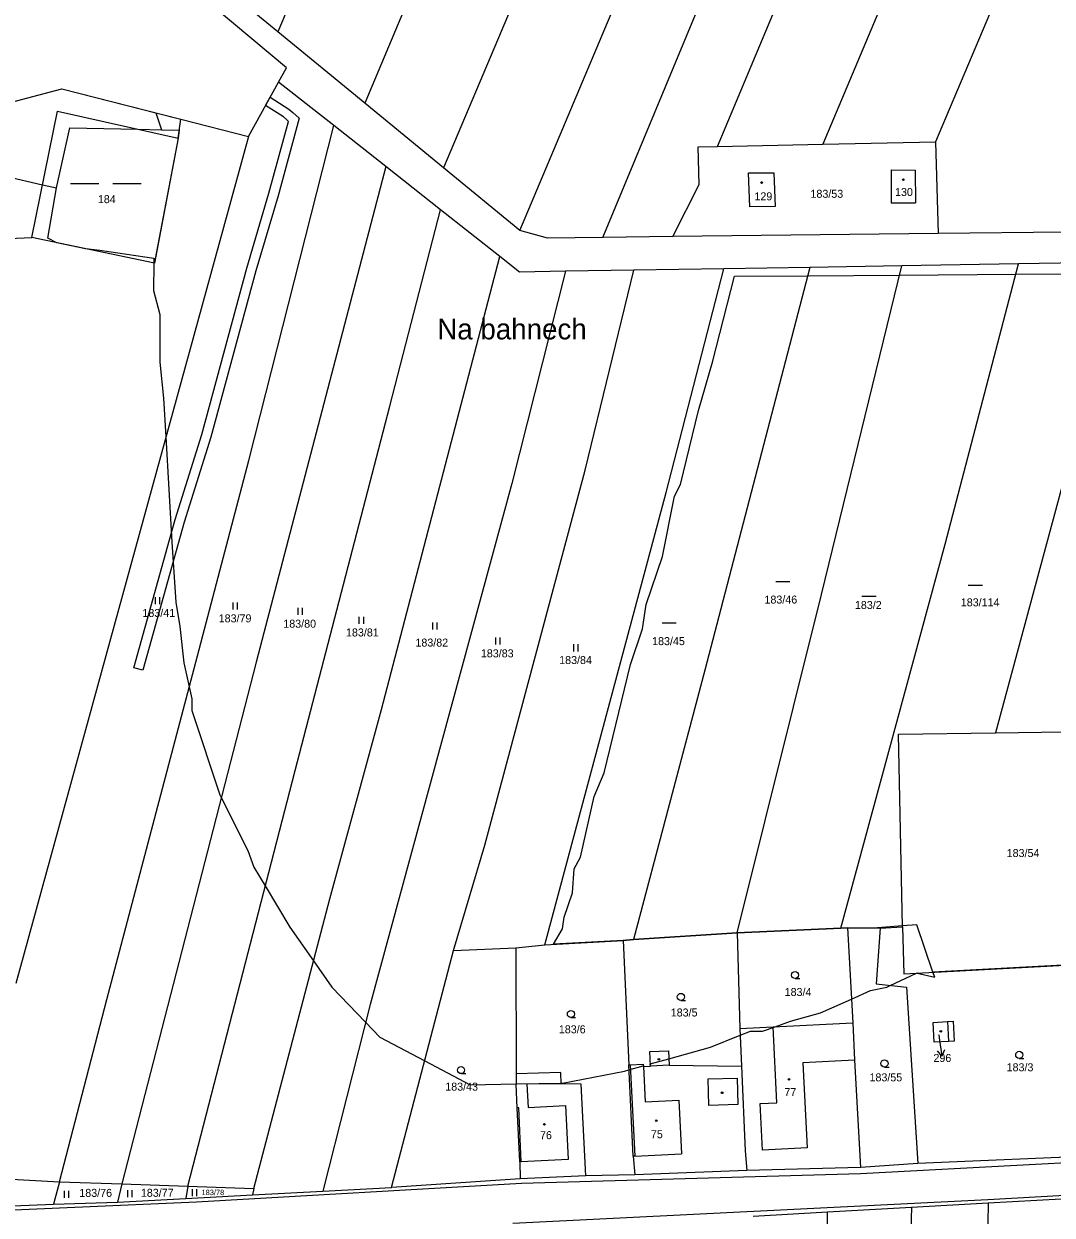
# Model space of a CAD drawing. Extents: x -747333 to -745433, y -1133152 to -1130600.
# Drawn here: x -747031.5 to -746813.1, y -1132285.5 to -1132032.4 of the extents above; entities that cross this region are included whole.
import ezdxf

# ---------------------------------------------------------------- set-up
doc = ezdxf.new("R2010")
doc.units = 0
for name, color, linetype in [('Vrstva 1', 7, 'Continuous'), ('Vrstva 13', 7, 'Continuous'), ('Vrstva 15', 7, 'Continuous'), ('Vrstva 16', 7, 'Continuous'), ('Vrstva 18', 7, 'Continuous'), ('Vrstva 19', 7, 'Continuous'), ('Vrstva 25', 7, 'Continuous'), ('Vrstva 3', 7, 'Continuous'), ('Vrstva 30', 7, 'Continuous'), ('Vrstva 37', 7, 'Continuous'), ('Vrstva 4', 7, 'Continuous'), ('Vrstva 52', 7, 'Continuous'), ('Vrstva 6', 7, 'Continuous')]:
    doc.layers.add(name, color=color, linetype=linetype)

msp = doc.modelspace()

# ---------------------------------------------------------------- linework, layer by layer
at = {"layer": 'Vrstva 1'}
for points in [[(-746977.55, -1132034.06), (-746997.36, -1132017.78)], [(-746959.07, -1132049.24), (-746977.55, -1132034.06)], [(-746965.7, -1132053.97), (-746977.4, -1132044.75)], [(-746942.38, -1132062.95), (-746959.07, -1132049.24)], [(-747029.81, -1132077.77), (-747024.36, -1132050.95)], [(-747024.36, -1132050.95), (-746998.74, -1132056.7)], [(-746998.74, -1132056.7), (-746998.16, -1132052.61)], [(-746954.65, -1132062.68), (-746965.7, -1132053.97)], [(-746983.8, -1132056.28), (-747014.12, -1132166.6)], [(-746998.74, -1132056.7), (-747003.78, -1132083.21)], [(-746884.2, -1132058.41), (-746861.84, -1132057.93)], [(-746861.84, -1132057.93), (-746837.88, -1132057.42)], [(-746837.88, -1132057.42), (-746837.35, -1132076.92)], [(-746888.32, -1132058.5), (-746884.2, -1132058.41)], [(-746888.09, -1132066.49), (-746888.32, -1132058.5)], [(-746942.98, -1132071.88), (-746954.65, -1132062.68)], [(-746926.18, -1132076.31), (-746942.38, -1132062.95)], [(-746877.57, -1132064.03), (-746872.2, -1132064.03)], [(-746877.34, -1132071.25), (-746877.57, -1132064.03)], [(-746872.2, -1132064.03), (-746871.97, -1132071.17)], [(-746847.33, -1132063.4), (-746842.21, -1132063.47)], [(-746847.33, -1132063.4), (-746847.27, -1132070.42)], [(-746842.21, -1132063.47), (-746842.16, -1132070.38)], [(-746893.7, -1132077.54), (-746888.09, -1132066.49)], [(-746847.27, -1132070.42), (-746842.16, -1132070.38)], [(-746930.38, -1132081.81), (-746942.98, -1132071.88)], [(-746871.97, -1132071.17), (-746877.34, -1132071.25)], [(-747046.01, -1132078.5), (-747029.81, -1132077.77)], [(-747003.78, -1132083.21), (-747029.81, -1132077.77)], [(-746920.27, -1132077.92), (-746926.18, -1132076.31)], [(-746908.56, -1132077.75), (-746920.27, -1132077.92)], [(-746893.7, -1132077.54), (-746908.56, -1132077.75)], [(-746837.35, -1132076.92), (-746893.7, -1132077.54)], [(-746810.33, -1132076.62), (-746837.35, -1132076.92)], [(-746926.2, -1132085.11), (-746930.38, -1132081.81)], [(-746820.24, -1132083.39), (-746845.06, -1132083.8)], [(-746798.2, -1132083.02), (-746820.24, -1132083.39)], [(-746916.47, -1132084.95), (-746926.2, -1132085.11)], [(-746901.96, -1132084.72), (-746916.47, -1132084.95)], [(-746882.82, -1132084.41), (-746901.96, -1132084.72)], [(-746895.12, -1132131.95), (-746882.82, -1132084.41)], [(-746864.54, -1132084.11), (-746886.87, -1132169.67)], [(-746864.54, -1132084.11), (-746882.82, -1132084.41)], [(-746845.06, -1132083.8), (-746864.54, -1132084.11)], [(-746862.13, -1132153.61), (-746845.06, -1132083.8)], [(-746920.89, -1132228), (-746895.12, -1132131.95)], [(-746879.98, -1132225.48), (-746862.13, -1132153.61)], [(-747014.12, -1132166.6), (-747033.2, -1132236.24)], [(-746886.87, -1132169.67), (-746902.04, -1132226.9)], [(-746845.75, -1132183.3), (-746825.13, -1132182.99)], [(-746844.91, -1132224.19), (-746845.75, -1132183.3)], [(-746825.13, -1132182.99), (-746805.63, -1132182.7)], [(-746879.98, -1132225.48), (-746858.02, -1132224.47)], [(-746858.02, -1132224.47), (-746856.57, -1132224.4)], [(-746856.57, -1132224.4), (-746855.47, -1132244.6)], [(-746856.57, -1132224.4), (-746849.62, -1132224.47)], [(-746849.62, -1132224.47), (-746850.48, -1132236.32)], [(-746849.62, -1132224.47), (-746844.91, -1132224.19)], [(-746844.91, -1132224.19), (-746844.62, -1132234.18)], [(-746920.89, -1132228), (-746904.25, -1132227.12)], [(-746904.25, -1132227.12), (-746902.04, -1132226.9)], [(-746904.25, -1132227.12), (-746903.04, -1132253.55)], [(-746902.04, -1132226.9), (-746879.98, -1132225.48)], [(-746879.98, -1132225.48), (-746879.44, -1132245.79)], [(-746953.39, -1132279.59), (-746940.23, -1132229.26)], [(-746940.23, -1132229.26), (-746927.02, -1132228.69)], [(-746927.02, -1132228.69), (-746920.89, -1132228)], [(-746927.02, -1132228.69), (-746926.95, -1132255.46)], [(-746844.62, -1132234.18), (-746794.52, -1132231.47)], [(-746850.48, -1132236.32), (-746844.05, -1132237.04)], [(-746844.05, -1132237.04), (-746841.63, -1132274.45)], [(-746872.39, -1132245.44), (-746855.47, -1132244.6)], [(-746855.47, -1132244.6), (-746855.08, -1132252.52)], [(-746838.17, -1132248.72), (-746838.41, -1132244.5), (-746835.37, -1132244.32)], [(-746835.37, -1132244.32), (-746834.14, -1132244.25), (-746833.89, -1132248.47), (-746835.13, -1132248.54)], [(-746879.44, -1132245.79), (-746872.39, -1132245.44)], [(-746879.44, -1132245.79), (-746879.09, -1132253.81)], [(-746835.13, -1132248.54), (-746838.17, -1132248.72)], [(-746898.59, -1132250.72), (-746894.61, -1132250.52)], [(-746898.44, -1132253.81), (-746898.59, -1132250.72)], [(-746894.61, -1132250.52), (-746894.45, -1132253.61)], [(-746855.08, -1132252.52), (-746853.79, -1132275.31)], [(-746917.46, -1132255.18), (-746926.95, -1132255.46)], [(-746926.95, -1132255.46), (-746926.94, -1132257.7)], [(-746917.39, -1132257.53), (-746917.46, -1132255.18)], [(-746903.04, -1132253.55), (-746902.74, -1132253.53)], [(-746902.06, -1132272.95), (-746903.04, -1132253.55)], [(-746902.74, -1132253.53), (-746899.95, -1132253.39)], [(-746899.95, -1132253.39), (-746899.93, -1132253.89)], [(-746899.93, -1132253.89), (-746898.44, -1132253.81)], [(-746894.45, -1132253.61), (-746879.09, -1132253.81)], [(-746879.09, -1132253.81), (-746878.29, -1132271.82)], [(-746926.7, -1132262.67), (-746926.94, -1132257.7)], [(-746913.17, -1132257.6), (-746917.39, -1132257.53)], [(-746912.17, -1132277.09), (-746913.17, -1132257.6)], [(-746926.15, -1132274.1), (-746926.7, -1132262.67)], [(-746902.06, -1132272.95), (-746901.75, -1132276.88)], [(-746878.29, -1132271.82), (-746877.98, -1132275.95)], [(-746801.64, -1132272.79), (-746841.63, -1132274.45)], [(-746926.15, -1132274.1), (-746926.09, -1132277.74)], [(-746853.79, -1132275.31), (-746877.98, -1132275.95)], [(-746841.63, -1132274.45), (-746853.79, -1132275.31)], [(-746926.09, -1132277.74), (-746953.39, -1132279.59)], [(-746912.17, -1132277.09), (-746926.09, -1132277.74)], [(-746901.75, -1132276.88), (-746912.17, -1132277.09)], [(-746877.98, -1132275.95), (-746901.75, -1132276.88)], [(-746982.92, -1132281.16), (-746968.03, -1132280.37)], [(-746968.03, -1132280.37), (-746953.39, -1132279.59)], [(-747046, -1132283.98), (-747025.21, -1132283.12)], [(-747025.21, -1132283.12), (-747011.61, -1132282.68)], [(-747011.61, -1132282.68), (-746997.1, -1132281.91)], [(-746997.1, -1132281.91), (-746982.92, -1132281.16)], [(-746843.01, -1132283.74), (-746826.69, -1132282.8)], [(-746826.69, -1132282.8), (-746790.54, -1132280.83)], [(-746876.61, -1132285.67), (-746860.79, -1132284.76)], [(-746860.79, -1132284.76), (-746843.01, -1132283.74)]]:
    msp.add_lwpolyline(points, dxfattribs=at)
at = {"layer": 'Vrstva 13'}
for points in [[(-746975.74, -1132041.76), (-747025.04, -1132000.35)], [(-746977.4, -1132044.75), (-746975.74, -1132041.76)], [(-746983.8, -1132056.28), (-746977.4, -1132044.75)], [(-747087.7, -1132063.18), (-747023.43, -1132046.16)], [(-747023.43, -1132046.16), (-746998.16, -1132052.61)], [(-746998.16, -1132052.61), (-746983.8, -1132056.28)]]:
    msp.add_lwpolyline(points, dxfattribs=at)
at = {"layer": 'Vrstva 16'}
msp.add_line((-746835.971101, -1132250.310353), (-746836.521773, -1132251.706512), dxfattribs=at)
for points in [[(-746837.11, -1132247.75), (-746836.521773, -1132251.706512), (-746837.454793, -1132250.530938)], [(-746837.2, -1132247.17), (-746837.11, -1132247.75)]]:
    msp.add_lwpolyline(points, dxfattribs=at)
at = {"layer": 'Vrstva 25'}
for p, q in [((-747021.59, -1132066.27), (-747015.59, -1132066.27)), ((-747012.59, -1132066.27), (-747006.59, -1132066.27)), ((-746871.81, -1132150.81), (-746868.81, -1132150.81)), ((-746830.92, -1132151.63), (-746827.92, -1132151.63)), ((-747003.6, -1132154.18), (-747003.6, -1132155.68)), ((-747002.6, -1132155.68), (-747002.6, -1132154.18)), ((-746853.51, -1132153.99), (-746850.51, -1132153.99)), ((-746987.12, -1132155.32), (-746987.12, -1132156.82)), ((-746986.12, -1132156.82), (-746986.12, -1132155.32)), ((-746973.32, -1132156.46), (-746973.32, -1132157.96)), ((-746972.32, -1132157.96), (-746972.32, -1132156.46)), ((-746960.33, -1132158.32), (-746960.33, -1132159.82)), ((-746959.33, -1132159.82), (-746959.33, -1132158.32)), ((-746944.69, -1132159.52), (-746944.69, -1132161.02)), ((-746943.69, -1132161.02), (-746943.69, -1132159.52)), ((-746895.96, -1132159.65), (-746892.96, -1132159.65)), ((-746931.31, -1132162.76), (-746931.31, -1132164.26)), ((-746930.31, -1132164.26), (-746930.31, -1132162.76)), ((-746914.76, -1132164.18), (-746914.76, -1132165.68)), ((-746913.76, -1132165.68), (-746913.76, -1132164.18)), ((-746867.71, -1132235.19), (-746866.71, -1132235.19)), ((-746891.97, -1132239.83), (-746890.97, -1132239.83)), ((-746915.32, -1132243.47), (-746914.32, -1132243.47)), ((-746820.1, -1132252.15), (-746819.1, -1132252.15)), ((-746938.65, -1132255.39), (-746937.65, -1132255.39)), ((-746848.72, -1132253.98), (-746847.72, -1132253.98)), ((-747022.93, -1132280.26), (-747022.93, -1132281.76)), ((-747021.93, -1132281.76), (-747021.93, -1132280.26)), ((-747009.48, -1132280.11), (-747009.48, -1132281.61)), ((-747008.48, -1132281.61), (-747008.48, -1132280.11)), ((-746995.77, -1132279.95), (-746995.77, -1132281.45)), ((-746994.77, -1132281.45), (-746994.77, -1132279.95))]:
    msp.add_line(p, q, dxfattribs=at)
for centre, radius in [((-746844.71, -1132065.49), 0.174503), ((-746874.81, -1132066.1), 0.174503), ((-746867.71, -1132234.44), 0.75), ((-746891.97, -1132239.08), 0.75), ((-746915.32, -1132242.72), 0.75), ((-746836.76, -1132246.42), 0.174503), ((-746896.63, -1132252.34), 0.174503), ((-746848.72, -1132253.23), 0.75), ((-746820.1, -1132251.4), 0.75), ((-746938.65, -1132254.64), 0.75), ((-746869.01, -1132256.61), 0.174503), ((-746883.2, -1132259.46), 0.174503), ((-746897.18, -1132265.39), 0.174503), ((-746920.95, -1132266.17), 0.174503)]:
    msp.add_circle(centre, radius, dxfattribs=at)
at = {"layer": 'Vrstva 3'}
for points in [[(-746877.57, -1132064.03), (-746872.2, -1132064.03)], [(-746877.34, -1132071.25), (-746877.57, -1132064.03)], [(-746872.2, -1132064.03), (-746871.97, -1132071.17)], [(-746847.33, -1132063.4), (-746842.21, -1132063.47)], [(-746847.33, -1132063.4), (-746847.27, -1132070.42)], [(-746842.21, -1132063.47), (-746842.16, -1132070.38)], [(-746847.27, -1132070.42), (-746842.16, -1132070.38)], [(-746871.97, -1132071.17), (-746877.34, -1132071.25)], [(-746872.39, -1132245.44), (-746855.47, -1132244.6)], [(-746855.47, -1132244.6), (-746855.08, -1132252.52)], [(-746838.17, -1132248.72), (-746838.41, -1132244.5), (-746835.37, -1132244.32)], [(-746835.37, -1132244.32), (-746835.13, -1132248.54)], [(-746871.59, -1132261.57), (-746872.39, -1132245.44)], [(-746835.13, -1132248.54), (-746838.17, -1132248.72)], [(-746855.08, -1132252.52), (-746866.06, -1132253.06)], [(-746917.46, -1132255.18), (-746926.95, -1132255.46)], [(-746926.95, -1132255.46), (-746926.94, -1132257.7)], [(-746917.39, -1132257.53), (-746917.46, -1132255.18)], [(-746902.74, -1132253.53), (-746899.95, -1132253.39)], [(-746902.74, -1132253.53), (-746901.76, -1132272.93)], [(-746899.95, -1132253.39), (-746899.93, -1132253.89)], [(-746899.93, -1132253.89), (-746899.55, -1132261.35)], [(-746866.06, -1132253.06), (-746865.16, -1132271.17)], [(-746926.7, -1132262.67), (-746926.94, -1132257.7)], [(-746917.39, -1132257.53), (-746924.65, -1132257.59)], [(-746924.65, -1132257.59), (-746924.41, -1132262.56)], [(-746926.4, -1132262.66), (-746926.7, -1132262.67)], [(-746925.85, -1132274.09), (-746926.4, -1132262.66)], [(-746924.41, -1132262.56), (-746916.46, -1132262.18)], [(-746916.46, -1132262.18), (-746915.91, -1132273.61)], [(-746899.55, -1132261.35), (-746892.39, -1132260.99)], [(-746892.39, -1132260.99), (-746891.81, -1132272.43)], [(-746875.1, -1132261.74), (-746871.59, -1132261.57)], [(-746874.61, -1132271.64), (-746875.1, -1132261.74)], [(-746901.76, -1132272.93), (-746891.81, -1132272.43)], [(-746865.16, -1132271.17), (-746874.61, -1132271.64)], [(-746915.91, -1132273.61), (-746925.85, -1132274.09)]]:
    msp.add_lwpolyline(points, dxfattribs=at)
at = {"layer": 'Vrstva 30'}
for p, q in [((-746973, -1132052.45), (-746977.52, -1132068.92)), ((-746975.66, -1132052.74), (-746976.38, -1132052.13)), ((-746975.26, -1132053.11), (-746975.66, -1132052.74)), ((-746975.2, -1132050.51), (-746974.34, -1132051.24)), ((-746974.34, -1132051.24), (-746973, -1132052.45)), ((-746979.44, -1132068.38), (-746975.26, -1132053.11)), ((-746984.15, -1132084.28), (-746979.44, -1132068.38)), ((-746977.52, -1132068.92), (-746982.23, -1132084.82)), ((-746993.69, -1132119.64), (-746984.15, -1132084.28)), ((-746982.23, -1132084.82), (-746991.77, -1132120.2)), ((-746999.35, -1132137.69), (-746993.69, -1132119.64)), ((-746991.77, -1132120.2), (-746997.43, -1132138.25)), ((-747008.15, -1132169.16), (-746999.35, -1132137.69)), ((-746997.43, -1132138.25), (-747006.23, -1132169.7)), ((-747006.23, -1132169.7), (-747008.15, -1132169.16))]:
    msp.add_line(p, q, dxfattribs=at)
msp.add_lwpolyline([(-746976.38, -1132052.13), (-746980.17, -1132049.74), (-746979.2, -1132047.99), (-746975.2, -1132050.51)], dxfattribs=at)
at = {"layer": 'Vrstva 37'}
for centre in [(-746844.71, -1132065.49), (-746874.81, -1132066.1), (-746836.76, -1132246.42), (-746869.01, -1132256.61), (-746897.18, -1132265.39), (-746920.95, -1132266.17)]:
    msp.add_circle(centre, 0.174503, dxfattribs=at)
at = {"layer": 'Vrstva 4'}
for points in [[(-746835.37, -1132244.32), (-746835.13, -1132248.54)], [(-746871.59, -1132261.57), (-746872.39, -1132245.44)], [(-746855.08, -1132252.52), (-746866.06, -1132253.06)], [(-746902.74, -1132253.53), (-746901.76, -1132272.93)], [(-746899.93, -1132253.89), (-746899.55, -1132261.35)], [(-746894.45, -1132253.61), (-746898.44, -1132253.81)], [(-746866.06, -1132253.06), (-746865.16, -1132271.17)], [(-746917.39, -1132257.53), (-746924.65, -1132257.59)], [(-746924.65, -1132257.59), (-746924.41, -1132262.56)], [(-746886.2, -1132256.46), (-746879.99, -1132256.32)], [(-746886.05, -1132262.18), (-746886.2, -1132256.46)], [(-746879.99, -1132256.32), (-746879.84, -1132261.96)], [(-746926.4, -1132262.66), (-746926.7, -1132262.67)], [(-746925.85, -1132274.09), (-746926.4, -1132262.66)], [(-746924.41, -1132262.56), (-746916.46, -1132262.18)], [(-746916.46, -1132262.18), (-746915.91, -1132273.61)], [(-746899.55, -1132261.35), (-746892.39, -1132260.99)], [(-746892.39, -1132260.99), (-746891.81, -1132272.43)], [(-746879.84, -1132261.96), (-746886.05, -1132262.18)], [(-746875.1, -1132261.74), (-746871.59, -1132261.57)], [(-746874.61, -1132271.64), (-746875.1, -1132261.74)], [(-746901.76, -1132272.93), (-746902.06, -1132272.95)], [(-746901.76, -1132272.93), (-746891.81, -1132272.43)], [(-746865.16, -1132271.17), (-746874.61, -1132271.64)], [(-746853.8, -1132276.58), (-746771.51, -1132272.22)], [(-746915.91, -1132273.61), (-746925.85, -1132274.09)], [(-746925.83, -1132278.65), (-746853.8, -1132276.58)], [(-746994.84, -1132282.65), (-746925.83, -1132278.65)], [(-746790.3, -1132280.16), (-746826.79, -1132282.23)], [(-747046.57, -1132284.9), (-746994.84, -1132282.65)], [(-746826.79, -1132282.23), (-746927.68, -1132287.24)]]:
    msp.add_lwpolyline(points, dxfattribs=at)
at = {"layer": 'Vrstva 52'}
for points in [[(-747003.44, -1132051.26), (-746998.16, -1132052.61), (-746983.8, -1132056.28), (-746977.4, -1132044.75), (-746975.74, -1132041.76), (-747025.04, -1132000.35), (-747039.86, -1131988.12), (-747054.69, -1131975.89), (-747072.89, -1131966.47), (-747071.24, -1131964.51), (-747058.92, -1131949.83), (-747020.64, -1131903.85), (-746947.7, -1131816.25)], [(-747266.6, -1132133.02), (-747263.75, -1132103.85), (-747228.47, -1132092.15), (-747166.2, -1132081.01), (-747144.88, -1132077.08), (-747120.33, -1132072.66), (-747114.6, -1132071.63), (-747087.7, -1132063.18), (-747023.43, -1132046.16), (-747003.44, -1132051.26)], [(-747003.44, -1132051.26), (-747002.25, -1132054.88)], [(-747024.56, -1132067.25), (-747021.75, -1132054.5), (-747007.3, -1132054.78), (-747002.25, -1132054.88)], [(-747002.25, -1132054.88), (-746998.49, -1132054.95), (-746998.74, -1132056.7)], [(-746998.74, -1132056.7), (-747003.61, -1132082.29), (-747003.88, -1132082.25)], [(-747266.6, -1132133.02), (-747263.16, -1132129.01), (-747256.94, -1132121.75), (-747236.94, -1132109.37), (-747207.19, -1132099.13), (-747187.76, -1132094.33), (-747172.75, -1132090.63), (-747142.12, -1132085.12), (-747131.94, -1132082.63), (-747129.3, -1132082.17), (-747126.81, -1132081.75), (-747123, -1132080.5), (-747122.09, -1132080.32), (-747112.38, -1132078.38), (-747110.32, -1132077.94), (-747095.45, -1132074.75), (-747072.2, -1132069.77), (-747046.44, -1132064.25), (-747035.38, -1132064.75), (-747027.53, -1132066.56), (-747024.56, -1132067.25)], [(-747003.88, -1132082.25), (-747015.38, -1132080.5), (-747018.39, -1132080.16), (-747024.5, -1132078.88), (-747026.44, -1132077.88), (-747024.56, -1132067.25)], [(-747003.88, -1132082.25), (-747003.88, -1132083.19), (-747003.94, -1132089), (-747002.63, -1132094.13), (-747002.63, -1132104.25), (-747001.81, -1132111.88), (-747001.34, -1132120.11), (-747000.06, -1132142.5), (-746999.25, -1132155.25), (-746998.38, -1132160.38), (-746997.5, -1132168.13), (-746996.38, -1132173.2), (-746995.81, -1132175.75), (-746995.81, -1132178.25), (-746989.87, -1132196.13), (-746989.56, -1132196.76), (-746983.94, -1132208), (-746982.63, -1132211.5), (-746980.22, -1132215.52), (-746975, -1132224.25), (-746969.98, -1132231.41), (-746966.06, -1132237), (-746958.93, -1132244.44), (-746955.87, -1132247.62), (-746946.35, -1132252.65), (-746936.69, -1132257.75), (-746926.94, -1132257.56), (-746917.39, -1132257.38), (-746917.13, -1132257.38), (-746903.94, -1132254.87), (-746902.99, -1132254.61), (-746899.94, -1132253.75), (-746899.93, -1132253.89), (-746898.44, -1132253.81), (-746898.46, -1132253.34), (-746894.52, -1132252.23), (-746885.69, -1132249.75), (-746879.38, -1132247.24), (-746877.19, -1132246.37), (-746874.62, -1132246.37), (-746871.95, -1132245.42), (-746868.69, -1132244.25), (-746862.31, -1132242.5), (-746855.74, -1132239.56), (-746851.69, -1132237.75), (-746848.25, -1132237), (-746847.51, -1132236.65), (-746841.95, -1132234.04), (-746841.88, -1132234), (-746841.76, -1132234.03), (-746838.06, -1132234.87), (-746838.42, -1132233.84)], [(-746838.42, -1132233.84), (-746841.88, -1132223.75), (-746844.91, -1132223.98), (-746851.08, -1132224.46), (-746856.57, -1132224.4), (-746858.02, -1132224.47), (-746879.98, -1132225.48), (-746902.04, -1132226.9), (-746904.25, -1132227.12), (-746919.04, -1132227.9), (-746917.13, -1132224.63), (-746916.75, -1132222.12), (-746915, -1132217), (-746914.63, -1132211.88), (-746913.31, -1132209.38), (-746910.38, -1132196.5), (-746908.25, -1132191.5), (-746902.69, -1132168.5), (-746900.12, -1132160.87), (-746899.31, -1132155.75), (-746895.87, -1132145.5), (-746893.31, -1132132.75), (-746892.06, -1132130.25), (-746888.25, -1132114.5), (-746885.25, -1132104.25), (-746880.56, -1132086), (-746865, -1132085.89), (-746845.54, -1132085.76), (-746820.81, -1132085.58), (-746798.85, -1132085.43)], [(-746759.14, -1132222.5), (-746762.47, -1132230.28), (-746791.25, -1132245), (-746788.69, -1132231), (-746792.34, -1132231.29), (-746792.37, -1132231.29), (-746794.52, -1132231.46), (-746795.01, -1132231.5), (-746838.42, -1132233.84)]]:
    msp.add_lwpolyline(points, dxfattribs=at)
at = {"layer": 'Vrstva 6'}
for points in [[(-746935.54, -1131934.66), (-746977.55, -1132034.06)], [(-746913.99, -1131941.79), (-746959.07, -1132049.24)], [(-746894.14, -1131948.92), (-746942.38, -1132062.95)], [(-746926.18, -1132076.31), (-746875.37, -1131955.78)], [(-746908.56, -1132077.75), (-746860.1, -1131961.17)], [(-746884.2, -1132058.41), (-746845.67, -1131966.46)], [(-746826.1, -1131973.14), (-746861.84, -1132057.93)], [(-746805.37, -1131980.54), (-746837.88, -1132057.42)], [(-746983.73, -1132125.17), (-746965.7, -1132053.97)], [(-746954.65, -1132062.68), (-746982.16, -1132168)], [(-746953.76, -1132113.62), (-746942.98, -1132071.88)], [(-746955.56, -1132178), (-746930.38, -1132081.81)], [(-746835.83, -1132142.89), (-746820.24, -1132083.39)], [(-746798.2, -1132083.02), (-746825.13, -1132182.99)], [(-746916.47, -1132084.95), (-746927.88, -1132130.04)], [(-746912.31, -1132127.19), (-746901.96, -1132084.72)], [(-746973.89, -1132190.98), (-746953.76, -1132113.62)], [(-746995.01, -1132168), (-746983.73, -1132125.17)], [(-746933.58, -1132206.84), (-746912.31, -1132127.19)], [(-746927.88, -1132130.04), (-746957.98, -1132240.67)], [(-746858.02, -1132224.47), (-746835.83, -1132142.89)], [(-747013.85, -1132239.65), (-746995.01, -1132168)], [(-746982.16, -1132168), (-747010.67, -1132278.83)], [(-746966.54, -1132218.25), (-746955.56, -1132178)], [(-746996.68, -1132279.26), (-746973.89, -1132190.98)], [(-746940.23, -1132229.26), (-746933.58, -1132206.84)], [(-746982.63, -1132279.76), (-746966.54, -1132218.25)], [(-747023.94, -1132278.4), (-747013.85, -1132239.65)], [(-746957.98, -1132240.67), (-746968.03, -1132280.37)], [(-747044.43, -1132277.24), (-747023.94, -1132278.4)], [(-747023.94, -1132278.4), (-747025.21, -1132283.12)], [(-747023.94, -1132278.4), (-747010.67, -1132278.83)], [(-747010.67, -1132278.83), (-747011.61, -1132282.68)], [(-747010.67, -1132278.83), (-746996.68, -1132279.26)], [(-746996.68, -1132279.26), (-746997.1, -1132281.91)], [(-746996.68, -1132279.26), (-746982.63, -1132279.76)], [(-746982.63, -1132279.76), (-746982.92, -1132281.16)], [(-746826.69, -1132282.8), (-746827.45, -1132331.11)], [(-746861.69, -1132364.09), (-746860.79, -1132284.76)], [(-746843.01, -1132283.74), (-746843.82, -1132312.84)]]:
    msp.add_lwpolyline(points, dxfattribs=at)

# ---------------------------------------------------------------- texts
at = {"layer": 'Vrstva 15'}
msp.add_text('Na bahnech', height=4.4, dxfattribs=at).set_placement((-746943.69521, -1132099.42))
at = {"layer": 'Vrstva 16'}
msp.add_text('296', height=1.7, dxfattribs=at).set_placement((-746838.318787, -1132252.91))
at = {"layer": 'Vrstva 18'}
for s, height, p in [('183/53', 1.7, (-746864.44, -1132069.33)), ('184', 1.7, (-747015.78, -1132070.47)), ('183/46', 1.7, (-746874.21, -1132155.53)), ('183/41', 1.7, (-747006.32, -1132158.38)), ('183/2', 1.7, (-746855, -1132156.69)), ('183/114', 1.7, (-746832.51, -1132156.12)), ('183/79', 1.7, (-746990.12, -1132159.52)), ('183/80', 1.7, (-746976.4, -1132160.66)), ('183/81', 1.7, (-746963.08, -1132162.52)), ('183/82', 1.7, (-746948.34, -1132164.67)), ('183/45', 1.7, (-746898.07, -1132164.36)), ('183/83', 1.7, (-746934.44, -1132166.96)), ('183/84', 1.7, (-746917.81, -1132168.38)), ('183/54', 1.7, (-746822.77, -1132209.38)), ('183/4', 1.7, (-746869.92, -1132238.9)), ('183/5', 1.7, (-746894.11, -1132243.25)), ('183/6', 1.7, (-746917.88, -1132246.82)), ('183/55', 1.7, (-746851.9, -1132257.03)), ('183/3', 1.7, (-746822.78, -1132254.89)), ('183/43', 1.7, (-746942, -1132259)), ('183/76', 1.7, (-747019.72, -1132281.57)), ('183/77', 1.7, (-747006.65, -1132281.55)), ('183/78', 1.14, (-746993.76, -1132281.19))]:
    msp.add_text(s, height=height, dxfattribs=at).set_placement(p)
at = {"layer": 'Vrstva 19'}
for s, height, p in [('129', 1.7, (-746876.34, -1132069.87)), ('130', 1.7, (-746846.48, -1132068.95)), ('296', 0.1, (-746837.44, -1132247.19)), ('77', 1.7, (-746869.99, -1132260.17)), ('76', 1.7, (-746921.88, -1132269.31)), ('75', 1.7, (-746898.33, -1132269.1))]:
    msp.add_text(s, height=height, dxfattribs=at).set_placement(p)

doc.saveas('drawing.dxf')
